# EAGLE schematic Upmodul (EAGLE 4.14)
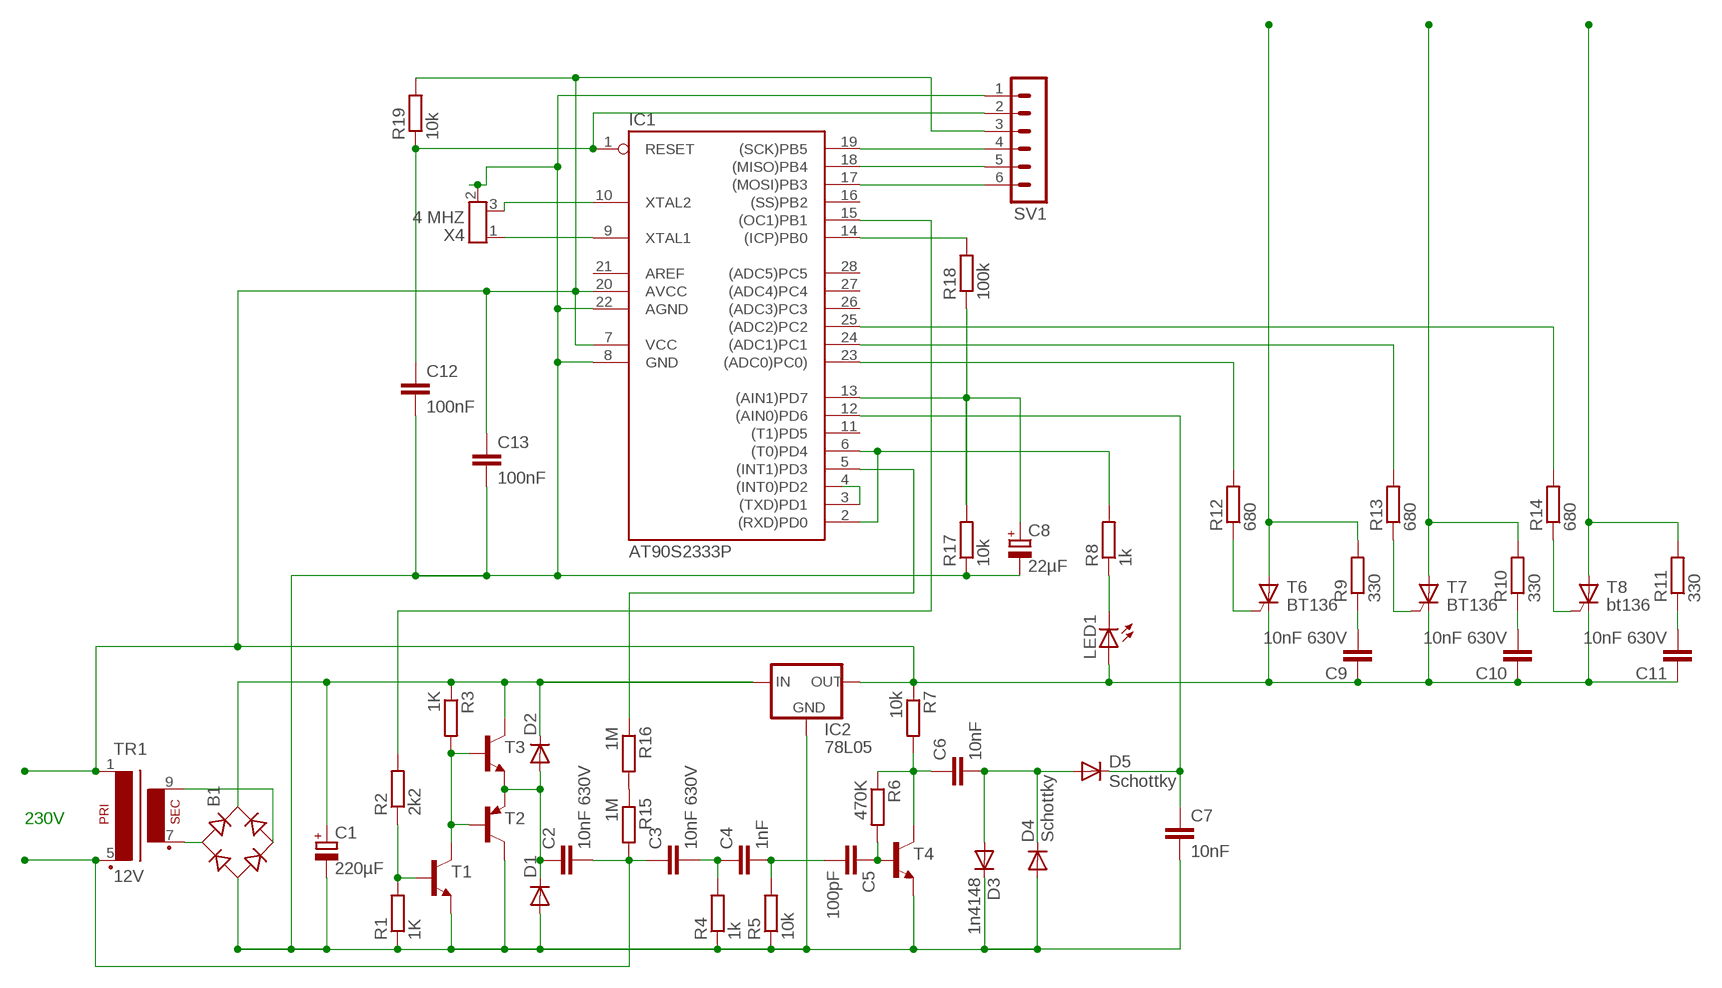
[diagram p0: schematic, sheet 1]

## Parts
B1  B-DIL  [B-DIL]
C1  220µF  CPOL-EUE5-10.5  [E5-10,5]
C2  10nF 630V  C-EU102-043X133  [C102-043X133]
C3  10nF 630V  C-EU102-043X133  [C102-043X133]
C4  1nF  C-EU025-024X044  [C025-024X044]
C5  100pF  C-EU050-024X044  [C050-024X044]
C6  10nF  C-EU025-024X044  [C025-024X044]
C7  10nF  C-EU050-024X044  [C050-024X044]
C8  22µF  CPOL-EUE5-10.5  [E5-10,5]
C9  10nF 630V  C-EU102-043X133  [C102-043X133]
C10  10nF 630V  C-EU102-043X133  [C102-043X133]
C11  10nF 630V  C-EU102-043X133  [C102-043X133]
C12  100nF  C-EU050-024X044  [C050-024X044]
C13  100nF  C-EU050-024X044  [C050-024X044]
D1  DIODE-D-5  [D-5]
D2  DIODE-D-2.5  [D-2.5]
D3  1n4148  DIODE-D-2.5  [D-2.5]
D4  Schottky  DIODE-D-2.5  [D-2.5]
D5  Schottky  DIODE-D-2.5  [D-2.5]
IC1  AT90S2333P  [DIL28-3]
IC2  78L05  78XXS  [78XXS]
LED1  LED3MM  [LED3MM]
R1  1K  R-EU_0207/5V  [0207/5V]
R2  2k2  R-EU_0207/5V  [0207/5V]
R3  1K  R-EU_0207/2V  [0207/2V]
R4  1k  R-EU_0207/5V  [0207/5V]
R5  10k  R-EU_0207/5V  [0207/5V]
R6  470K  R-EU_0207/2V  [0207/2V]
R7  10k  R-EU_0207/2V  [0207/2V]
R8  1k  R-EU_0207/5V  [0207/5V]
R9  330  R-EU_0207/5V  [0207/5V]
R10  330  R-EU_0207/5V  [0207/5V]
R11  330  R-EU_0207/5V  [0207/5V]
R12  680  R-EU_0207/5V  [0207/5V]
R13  680  R-EU_0207/5V  [0207/5V]
R14  680  R-EU_0207/5V  [0207/5V]
R15  1M  R-EU_0207/2V  [0207/2V]
R16  1M  R-EU_0207/2V  [0207/2V]
R17  10k  R-EU_0207/2V  [0207/2V]
R18  100k  R-EU_0207/2V  [0207/2V]
R19  10k  R-EU_0207/2V  [0207/2V]
SV1  MA06-1  [MA06-1]
T1  BC547A-NPN-TO92-EBC  [TO92-EBC]
T2  BC558A-PNP-TO92-EBC  [TO92-EBC]
T3  BC547A-NPN-TO92-EBC  [TO92-EBC]
T4  BC547A-NPN-TO92-EBC  [TO92-EBC]
T6  BT136  TIC126  [TO220CS]
T7  BT136  TIC126  [TO220CS]
T8  bt136  TIC126  [TO220CS]
TR1  12V  EI30-1  [EI30-1]
X4  4 MHZ  RESONZTT  [RESONZTT]

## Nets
5V: C9.1 C10.1 C11.1 C13.1 IC1.7(VCC) IC1.20(AVCC) IC2.OUT LED1.A R7.1 R19.2 SV1.3 T6.C T7.C T8.C TR1.1
GND1: B1.- C1.- C7.2 C8.- C12.2 C13.2 D1.A D3.C D4.A IC1.8(GND) IC1.22(AGND) IC2.GND R1.1 R4.1 R5.1 R17.1 SV1.1 T1.E T2.C T4.E X4.2(GND)
N$1: R1.2 R2.1 T1.B
N$2: C7.1 D5.C IC1.12((AIN0)PD6)
N$3: C6.1 R6.1 R7.2 T4.C
N$4: C6.2 D3.A D4.C D5.A
N$5: IC1.15((OC1)PB1) R2.2
N$6: C5.1 R6.2 T4.B
N$7: IC1.3((TXD)PD1) IC1.4((INT0)PD2)
N$8: IC1.5((INT1)PD3) R16.1
N$9: C2.2 C3.1 R15.2 TR1.5
N$10: IC1.17((MOSI)PB3) SV1.6
N$11: C12.1 IC1.1(RESET) R19.1 SV1.2
N$12: LED1.K(C) R8.1
N$13: C2.1 D1.C D2.A T2.E T3.E
N$14: B1.+ C1.+ D2.C IC2.IN R3.1 T3.C
N$15: R3.2 T1.C T2.B T3.B
N$16: IC1.18((MISO)PB4) SV1.5
N$17: IC1.19((SCK)PB5) SV1.4
N$18: C9.2 R9.1
N$19: B1.AC1 TR1.7
N$21: C10.2 R10.1
N$22: C11.2 R11.1
N$23: R15.1 R16.2
N$24: R9.2 T6.A
N$25: R10.2 T7.A
N$26: R11.2 T8.A
N$27: R12.1 T6.G
N$28: R13.1 T7.G
N$29: R14.1 T8.G
N$30: IC1.23((ADC0)PC0)) R12.2
N$31: IC1.24((ADC1)PC1) R13.2
N$32: IC1.25((ADC2)PC2) R14.2
N$33: C4.2 C5.2 R5.2
N$34: IC1.2((RXD)PD0) IC1.6((T0)PD4) R8.2
N$35: C8.+ IC1.13((AIN1)PD7) R17.2 R18.1
N$36: IC1.14((ICP)PB0) R18.2
N$37: C3.2 C4.1 R4.2
N$38: B1.AC2 TR1.9
N$52: IC1.9(XTAL1) X4.1(X1)
N$53: IC1.10(XTAL2) X4.3(X2)
Unconnected: IC1.11((T1)PD5) IC1.16((SS)PB2) IC1.26((ADC3)PC3) IC1.27((ADC4)PC4) IC1.28((ADC5)PC5)

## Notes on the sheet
- 230V

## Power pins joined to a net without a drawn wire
AREF: IC1.21(AREF)

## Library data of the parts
B1 = rectifier:B-DIL: RECTIFIER
C1 C8 = rcl:CPOL-EU: POLARIZED CAPACITOR, European symbol
C2-C7 C9-C13 = rcl:C-EU: CAPACITOR, European symbol
D1-D5 = diode:DIODE-: DIODE
IC1 = atmel:AT90S2333P: MICROCONTROLLER 2 Kbytes FLASH 128 bytes SRAM 128 bytes EEPROM UART 6-channel 10-bit ADC
IC2 = v-reg:78XXS: VOLTAGE REGULATOR
LED1 = led:LED: LED
R1-R19 = rcl:R-EU_: RESISTOR, European symbol
SV1 = con-lstb:MA06-1: PIN HEADER
T1 T3 T4 = transistor:*-NPN-: NPN Transistror
T2 = transistor:*-PNP-: PNP Transistror
T6-T8 = triac:TIC126: THYRISTOR
TR1 = trafo:EI30-1: TRANSFORMER 1 primary winding, 1 secondary winding ERA
X4 = ADS:RESONZTT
